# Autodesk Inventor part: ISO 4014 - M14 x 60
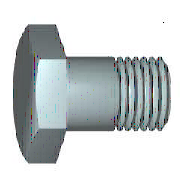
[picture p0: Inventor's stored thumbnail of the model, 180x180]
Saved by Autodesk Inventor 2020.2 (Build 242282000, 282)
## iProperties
Manager: www.cadconsulting.pl
Company: Fabian Stasiak CAD Consulting
Created: 2016-02
Part Number: ISO 4014 - M14 x 60
Material: Stal nierdzewna 440C
Description: Śruba z łbem sześciokątnym - Klasa dokładności A i B
Document SubType Name: Modeling
Standard: ISO 4014
Designer: F.Stasiak
Standard Revision: Fourth edition 2011-03-15
Standards Organization: ISO
Language: pl-PL
Size Designation: M14 x 60
Categories: <MemberInstance><Categories><Category DisplayName="Mocowania" InternalName="e4da775c-781d-43d5-af7c-5136215cf5a6" Mnemonic="FSTN"><Category DisplayName="Śruby"
Density: 7.75 g/cm^3
Appearance: Częściowo polerowana
IsCustomPart: 0
Author: F.Stasiak
Subject: Zbiór ćwiczeń. Autodesk Inventor 2020. Kurs podstawowy
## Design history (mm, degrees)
sketch "Szkic1"
  geometry: L1 (0, 9.82)-(0, 7); L2 (26, 7)-(60, 7); L3 (60, 7)-(60, 0); L4 (60, 0)-(-0.6, 0); L5 (-12.72, 0)-(72.12, 0) reference; L6 (-0.6, 0)-(-0.6, 9.82); L7 (-0.6, 9.82)-(0, 9.82); L8 (26, 7)-(24.773, 7); L9 (24.773, 7)-(0, 7); L10 (0, -1.964)-(0, 11.784) reference
  constraints: 16 end point, 2 collinear, 2 perpendicular, 1 parallel
  dimensions: "d0" = 60 distance between parallel lines of L3 L1 (= NLG); "d1" = 34 distance from line of L2.start L3 (= GEL); "d2" = 14 diameter of L2 L4 (= GD); "d9" = 0.6001 distance between parallel lines of L6 L1 (computed from SD); "d10" = 19.64 diameter of L7 L4 (= SD2); "d13" = 1.227 distance of L2.start L8.end (computed from GAL); "d14" = 14 diameter of L9 L4 (= BDM)
revolve "Bryła" sketch "Szkic1" stored, may be unused: angle "d12" = 90 deg
sketch "Szkic2"
  geometry: L1 (0, 12.124)-(10.5, 6.062); L2 (10.5, 6.062)-(10.5, -6.062); L3 (10.5, -6.062)-(0, -12.124); L4 (0, -12.124)-(-10.5, -6.062); L5 (-10.5, -6.062)-(-10.5, 6.062); L6 (-10.5, 6.062)-(0, 12.124); 2 further points
  constraints: 12 end point, 1 coincident, 1 vertical, 11 other
  dimensions: "d11" = 21 distance between parallel lines of L5 L2 (= SW)
extrude "Głowica" join sketch "Szkic2" distance "d3" = 8.2 (= KOH - SD); taper "d4" = 0 deg
sketch "Szkic4"
  geometry: L1 (-8.8, 10.5)-(-8.8, 12.124); L2 (-8.8, 12.124)-(-7.862, 12.124); L3 (-7.862, 12.124)-(-8.8, 10.5); L4 (-10.44, 0)-(1.04, 0) reference; L5 (-0.6, 12.124)-(-8.8, 12.124) reference; L6 (-8.8, 6.062)-(-8.8, 12.124) reference
  constraints: 6 end point, 2 collinear, 1 perpendicular, 1 vertical
  dimensions: "d5" = 30 deg angle of L3 L1 (= ANG1); "d19" = 21 diameter of L1.start L4 (= SW0)
revolve "Faza1" sketch "Szkic4" stored, may be unused: angle "d21" = 90 deg
workplane "Work Plane1"
body "Solid1"
feature "Gwint" dims "d15" = 34 (= GEL), "d16" = 0
chamfer "Faza2" distance "d6" = 1.2269 (= -0.5 x SPD + 0.5 x GD); stored, may be unused: second distance "d7" = 1.227 (computed from GUL), angle "d55" = 45 deg
other parameters: "NLG" = 60 [user parameter; used in 1 equation term], "GD" = 14 (= NND) [user parameter; used in 2 equation terms], "BDM" = 14 (= NND) [user parameter; used in 1 equation term], "KOH" = 8.8 [user parameter; used in 1 equation term], "GEL" = 34 [user parameter; used in 2 equation terms], "SW" = 21 [user parameter; used in 3 equation terms], "SW0" = 21 (= SW) [user parameter; used in 1 equation term], "SPD" = 11.5462 (= NND - 1.2269 x PTC) [user parameter; used in 1 equation term], "SD2" = 19.64 [user parameter; used in 2 equation terms], "SD" = 0.6 [user parameter; used in 2 equation terms], "ANG1" = 30 deg [user parameter; used in 1 equation term], "GAL" = 1.2269 (= 0.61345 x PTC) [user parameter; used in 1 equation term], "GUL" = 1.2269 (= 0.61345 x PTC) [user parameter; used in 1 equation term], "d8" = 0, "RR" = 0.6 [user parameter], "d57" = 0, "d58" = 0, "TPU" = 5 (computed from PTC) [user parameter], "GD1" = 11.5462 (= THREADDIA - 1.2269 x PTC) [user parameter], "THREADDIA" = 14 [user parameter; used in 1 equation term], "SDH" = 19.64 (= SD2) [user parameter], "TOA" = 30 deg [user parameter], "PTC" = 2 [user parameter; used in 5 equation terms], "NND" = 14 [user parameter; used in 3 equation terms], "E0" = 24.255 (= 1.155 x SW) [user parameter]
